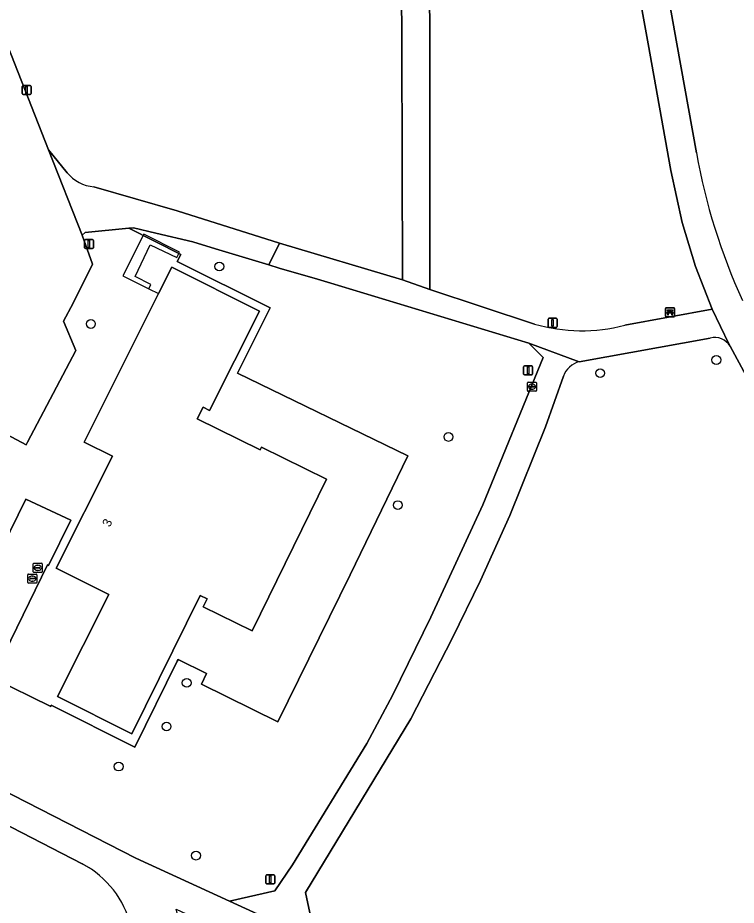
# Model space of a CAD drawing. Extents: x 162417 to 163722, y 384268 to 385417.
# Drawn here: x 162665 to 162744.1, y 384905.1 to 385002.9 of the extents above; entities that cross this region are included whole.
import ezdxf

# ---------------------------------------------------------------- set-up
doc = ezdxf.new("R2010")
doc.units = 0
for name, color, linetype in [('IMGEO_Bank', 7, 'Continuous'), ('IMGEO_Boom', 7, 'Continuous'), ('IMGEO_Erf', 7, 'Continuous'), ('IMGEO_Gemengd_bos', 7, 'Continuous'), ('IMGEO_Groenvoorziening', 7, 'Continuous'), ('IMGEO_Haag', 7, 'Continuous'), ('IMGEO_Hek', 7, 'Continuous'), ('IMGEO_Kolk', 7, 'Continuous'), ('IMGEO_Lichtmast', 7, 'Continuous'), ('IMGEO_Loofbos', 7, 'Continuous'), ('IMGEO_Pand', 7, 'Continuous'), ('IMGEO_Pand_nummerreeks', 7, 'Continuous'), ('IMGEO_Rijbaan_lokaal_gesloten', 7, 'Continuous'), ('IMGEO_Rioolput', 7, 'Continuous'), ('IMGEO_Voetpad_gesloten', 7, 'Continuous'), ('IMGEO_Voetpad_halfverhard', 7, 'Continuous')]:
    doc.layers.add(name, color=color, linetype=linetype)

msp = doc.modelspace()

# ---------------------------------------------------------------- linework, layer by layer
at = {"layer": 'IMGEO_Bank'}
for p, q in [((162736.32, 384969.985), (162736.32, 384970.826)), ((162736.32, 384970.826), (162736.32, 384969.985)), ((162736.395, 384970.91), (162737.236, 384970.91)), ((162737.236, 384970.91), (162736.395, 384970.91)), ((162736.629, 384970.416), (162736.629, 384970.522)), ((162736.673, 384970.522), (162736.673, 384970.416)), ((162736.961, 384970.528), (162736.679, 384970.528)), ((162736.679, 384970.41), (162736.961, 384970.41)), ((162736.967, 384970.416), (162736.967, 384970.522)), ((162737.011, 384970.522), (162737.011, 384970.416)), ((162737.32, 384970.835), (162737.32, 384969.994)), ((162737.32, 384969.994), (162737.32, 384970.835)), ((162737.245, 384969.91), (162736.404, 384969.91)), ((162736.404, 384969.91), (162737.245, 384969.91)), ((162737.017, 384970.308), (162736.624, 384970.308))]:
    msp.add_line(p, q, dxfattribs=at)
for points in [[(162736.567, 384970.308), (162736.425, 384970.308), (162736.537, 384970.41), (162736.623, 384970.41)], [(162736.623, 384970.528), (162736.537, 384970.528), (162736.537, 384970.689), (162737.1, 384970.689), (162737.1, 384970.528), (162737.017, 384970.528)], [(162737.017, 384970.41), (162737.1, 384970.41), (162737.212, 384970.308), (162737.073, 384970.308)], [(162736.617, 384970.301), (162736.617, 384970.094), (162736.574, 384970.094), (162736.574, 384970.301)], [(162737.067, 384970.301), (162737.067, 384970.094), (162737.023, 384970.094), (162737.023, 384970.301)]]:
    msp.add_lwpolyline(points, dxfattribs=at)
for centre, radius, start, end in [((162736.398, 384970.832), 0.0779, 92.4484, 184.28452), ((162736.398, 384970.832), 0.0779, 92.4484, 184.28452), ((162736.622, 384970.521), 0.00671, 2.89567, 87.10433), ((162736.622, 384970.417), 0.00671, 272.89567, 357.10433), ((162736.679, 384970.521), 0.00671, 92.89567, 177.10433), ((162736.679, 384970.417), 0.00671, 182.89567, 267.10433), ((162736.961, 384970.521), 0.00671, 2.89567, 87.10433), ((162736.961, 384970.417), 0.00671, 272.89567, 357.10433), ((162737.018, 384970.521), 0.00671, 92.89567, 177.10433), ((162737.018, 384970.417), 0.00671, 182.89567, 267.10433), ((162737.242, 384970.832), 0.0779, 2.4484, 94.28452), ((162737.242, 384970.832), 0.0779, 2.4484, 94.28452), ((162736.398, 384969.988), 0.0779, 182.4484, 274.28452), ((162736.398, 384969.988), 0.0779, 182.4484, 274.28452), ((162736.567, 384970.301), 0.00671, 2.89567, 87.10433), ((162736.624, 384970.301), 0.00671, 92.89567, 177.10433), ((162737.016, 384970.301), 0.00671, 2.89567, 87.10433), ((162737.073, 384970.301), 0.00671, 92.89567, 177.10433), ((162737.242, 384969.988), 0.0779, 272.4484, 4.28452), ((162737.242, 384969.988), 0.0779, 272.4484, 4.28452)]:
    msp.add_arc(centre, radius, start, end, dxfattribs=at)
at = {"layer": 'IMGEO_Boom'}
for centre in [(162687.199, 384975.461), (162673.043, 384969.131), (162741.935, 384965.159), (162729.134, 384963.709), (162712.429, 384956.683), (162706.852, 384949.167), (162683.603, 384929.586), (162681.378, 384924.773), (162676.1, 384920.36), (162684.623, 384910.552)]:
    msp.add_circle(centre, 0.489, dxfattribs=at)
at = {"layer": 'IMGEO_Erf'}
msp.add_lwpolyline([(162658.984, 384935.79), (162665.87, 384949.817), (162670.825, 384947.525), (162668.388, 384942.524), (162668.279, 384942.581), (162662.168, 384930.151), (162668.625, 384926.977), (162668.685, 384927.112), (162677.9, 384922.487), (162682.565, 384931.955), (162682.641, 384932.158), (162685.793, 384930.619), (162685.237, 384929.448), (162693.634, 384925.29), (162701.607, 384941.49), (162707.971, 384954.6), (162689.204, 384963.718), (162692.784, 384970.914), (162682.547, 384976.006), (162682.943, 384976.767), (162677.219, 384979.675), (162672.421, 384979.213), (162672.076, 384978.896), (162673.226, 384975.731), (162671.101, 384971.409), (162670.042, 384969.431), (162671.375, 384966.217), (162666.08, 384956.114), (162665.925, 384955.818), (162663.79, 384956.941)], dxfattribs=at)
msp.add_lwpolyline([(162675.411, 384954.553), (162672.293, 384956.119), (162680.502, 384972.471), (162681.96, 384975.375), (162691.61, 384970.53), (162686.115, 384959.587), (162685.399, 384959.947), (162684.764, 384958.682), (162691.707, 384955.263), (162691.848, 384955.55), (162698.989, 384952.032), (162690.809, 384935.31), (162685.419, 384937.946), (162685.859, 384938.845), (162685.081, 384939.225), (162677.556, 384923.953), (162669.362, 384928.066), (162675.012, 384939.32), (162669.222, 384942.227)], close=True, dxfattribs=at)
at = {"layer": 'IMGEO_Gemengd_bos'}
msp.add_lwpolyline([(162672.07, 384909.65), (162657.635, 384917.104), (162642.404, 384902.325), (162625.393, 384873.785), (162612.197, 384851.361), (162616.439, 384832.825)], dxfattribs=at)
for centre, radius, start, end in [((162667.115, 384900.122), 10.739, 56.1084, 62.52035), ((162667.261, 384900.356), 10.464, 7.41169, 56.05936)]:
    msp.add_arc(centre, radius, start, end, dxfattribs=at)
at = {"layer": 'IMGEO_Groenvoorziening'}
for points in [[(162649.362, 384924.906), (162677.988, 384910.273), (162688.32, 384905.515), (162693.292, 384906.669), (162695.237, 384909.513), (162703.447, 384922.914), (162706.318, 384928.257), (162710.486, 384936.828), (162716.223, 384949.194), (162722.864, 384965.432), (162721.277, 384966.997), (162699.469, 384973.623), (162698.022, 384974.047), (162693.785, 384975.287), (162692.629, 384975.638), (162686.775, 384977.414), (162684.286, 384978.175), (162680.206, 384979.142), (162677.723, 384979.724), (162677.219, 384979.675), (162682.943, 384976.767), (162682.547, 384976.006), (162692.784, 384970.914), (162689.204, 384963.718), (162707.971, 384954.6), (162701.607, 384941.49), (162693.634, 384925.29), (162685.237, 384929.448), (162685.793, 384930.619), (162682.641, 384932.158), (162682.565, 384931.955), (162677.9, 384922.487), (162668.685, 384927.112), (162668.625, 384926.977), (162662.168, 384930.151), (162668.279, 384942.581), (162668.388, 384942.524), (162670.825, 384947.525), (162665.87, 384949.817), (162658.984, 384935.79)], [(162741.248, 384967.575), (162726.84, 384964.964)], [(162766.925, 384907.1), (162768.008, 384909.584), (162768.293, 384911.192), (162767.743, 384912.987), (162766.989, 384912.798), (162765.701, 384916.53), (162766.445, 384916.8), (162765.082, 384920.804), (162760.396, 384932.895), (162758.923, 384936.287), (162751.438, 384951.872), (162749.254, 384955.923), (162743.449, 384966.69)], [(162725.09, 384963.368), (162723.123, 384957.808), (162719.181, 384948.018), (162715.956, 384940.876), (162712.852, 384934.463), (162708.293, 384925.612), (162696.695, 384906.49), (162697.815, 384901.146)]]:
    msp.add_lwpolyline(points, dxfattribs=at)
for centre, radius, start, end in [((162741.754, 384965.653), 1.987, 31.44635, 104.74452), ((162727.491, 384962.493), 2.556, 104.75993, 159.9697)]:
    msp.add_arc(centre, radius, start, end, dxfattribs=at)
at = {"layer": 'IMGEO_Haag'}
msp.add_lwpolyline([(162679.445, 384973.002), (162679.64, 384973.459), (162677.921, 384974.353), (162679.581, 384977.828), (162682.496, 384976.443), (162682.791, 384977.029), (162678.859, 384979.004), (162676.57, 384974.446)], close=True, dxfattribs=at)
at = {"layer": 'IMGEO_Hek'}
for points in [[(162682.496, 384976.443), (162682.791, 384977.029), (162678.859, 384979.004), (162676.57, 384974.446), (162679.445, 384973.002)], [(162679.445, 384973.002), (162680.502, 384972.471)]]:
    msp.add_lwpolyline(points, dxfattribs=at)
at = {"layer": 'IMGEO_Kolk'}
for p, q in [((162721.122, 384961.79), (162721.122, 384962.642)), ((162721.197, 384962.716), (162722.049, 384962.716)), ((162722.123, 384962.642), (162722.123, 384961.79)), ((162722.049, 384961.716), (162721.197, 384961.716)), ((162721.381, 384962.21), (162721.381, 384962.222)), ((162721.819, 384962.173), (162721.421, 384962.173)), ((162721.424, 384962.259), (162721.822, 384962.259)), ((162721.633, 384961.936), (162721.608, 384961.936)), ((162721.61, 384962.496), (162721.635, 384962.496)), ((162721.865, 384962.222), (162721.865, 384962.21))]:
    msp.add_line(p, q, dxfattribs=at)
for points in [[(162721.122, 384961.79), (162721.122, 384962.642)], [(162721.197, 384962.716), (162722.049, 384962.716)], [(162722.123, 384962.642), (162722.123, 384961.79)], [(162722.049, 384961.716), (162721.197, 384961.716)]]:
    msp.add_lwpolyline(points, dxfattribs=at)
for centre, radius, start, end in [((162721.199, 384962.64), 0.0765, 91.55205, 178.44795), ((162721.199, 384962.64), 0.0765, 91.55205, 178.44795), ((162722.047, 384962.64), 0.0765, 1.55205, 88.44795), ((162722.047, 384962.64), 0.0765, 1.55205, 88.44795), ((162721.199, 384961.792), 0.0765, 181.55205, 268.44795), ((162721.199, 384961.792), 0.0765, 181.55205, 268.44795), ((162721.421, 384962.219), 0.0403, 85.87752, 175.75265), ((162721.418, 384962.209), 0.0366, 178.93798, 274.71019), ((162721.822, 384962.216), 0.043, 264.86636, 352.45326), ((162721.826, 384962.221), 0.0386, 1.73085, 96.63898), ((162722.047, 384961.792), 0.0765, 271.55205, 358.44795), ((162722.047, 384961.792), 0.0765, 271.55205, 358.44795)]:
    msp.add_arc(centre, radius, start, end, dxfattribs=at)
for centre, major_axis, ratio, start_param, end_param in [((162721.609, 384962.216), (-0.387, 0.002), 0.722429, 4.712389, 7.853982), ((162721.634, 384962.216), (-0.39, 0.002), 0.717154, 1.570796, 4.712389)]:
    msp.add_ellipse(centre, major_axis=major_axis, ratio=ratio, start_param=start_param, end_param=end_param, dxfattribs=at)
at = {"layer": 'IMGEO_Lichtmast'}
for p, q in [((162665.471, 384994.503), (162665.471, 384995.303)), ((162665.471, 384995.303), (162665.471, 384994.503)), ((162665.571, 384995.403), (162666.361, 384995.403)), ((162666.361, 384995.403), (162665.571, 384995.403)), ((162666.461, 384995.303), (162666.461, 384994.503)), ((162666.461, 384994.503), (162666.461, 384995.303)), ((162666.361, 384994.403), (162665.571, 384994.403)), ((162665.571, 384994.403), (162666.361, 384994.403)), ((162672.335, 384977.534), (162672.335, 384978.334)), ((162672.335, 384978.334), (162672.335, 384977.534)), ((162672.435, 384978.434), (162673.225, 384978.434)), ((162673.225, 384978.434), (162672.435, 384978.434)), ((162673.325, 384978.334), (162673.325, 384977.534)), ((162673.325, 384977.534), (162673.325, 384978.334)), ((162673.225, 384977.434), (162672.435, 384977.434)), ((162672.435, 384977.434), (162673.225, 384977.434)), ((162723.4, 384968.853), (162723.4, 384969.653)), ((162723.4, 384969.653), (162723.4, 384968.853)), ((162723.5, 384969.753), (162724.29, 384969.753)), ((162724.29, 384969.753), (162723.5, 384969.753)), ((162724.39, 384969.653), (162724.39, 384968.853)), ((162724.39, 384968.853), (162724.39, 384969.653)), ((162724.29, 384968.753), (162723.5, 384968.753)), ((162723.5, 384968.753), (162724.29, 384968.753)), ((162720.708, 384963.614), (162720.708, 384964.414)), ((162720.708, 384964.414), (162720.708, 384963.614)), ((162720.808, 384964.514), (162721.598, 384964.514)), ((162721.598, 384964.514), (162720.808, 384964.514)), ((162721.698, 384964.414), (162721.698, 384963.614)), ((162721.698, 384963.614), (162721.698, 384964.414)), ((162721.598, 384963.514), (162720.808, 384963.514)), ((162720.808, 384963.514), (162721.598, 384963.514)), ((162692.305, 384907.527), (162692.305, 384908.327)), ((162692.305, 384908.327), (162692.305, 384907.527)), ((162692.405, 384908.427), (162693.195, 384908.427)), ((162693.195, 384908.427), (162692.405, 384908.427)), ((162693.295, 384908.327), (162693.295, 384907.527)), ((162693.295, 384907.527), (162693.295, 384908.327)), ((162693.195, 384907.427), (162692.405, 384907.427)), ((162692.405, 384907.427), (162693.195, 384907.427))]:
    msp.add_line(p, q, dxfattribs=at)
for points in [[(162665.891, 384995.278), (162666.041, 384995.278), (162666.041, 384994.528), (162665.891, 384994.528), (162665.891, 384995.278)], [(162672.755, 384978.309), (162672.905, 384978.309), (162672.905, 384977.559), (162672.755, 384977.559), (162672.755, 384978.309)], [(162723.82, 384969.628), (162723.97, 384969.628), (162723.97, 384968.878), (162723.82, 384968.878), (162723.82, 384969.628)], [(162721.128, 384964.389), (162721.278, 384964.389), (162721.278, 384963.639), (162721.128, 384963.639), (162721.128, 384964.389)], [(162692.725, 384908.302), (162692.875, 384908.302), (162692.875, 384907.552), (162692.725, 384907.552), (162692.725, 384908.302)]]:
    msp.add_lwpolyline(points, dxfattribs=at)
for centre, start, end in [((162665.571, 384995.303), 90, 180), ((162665.571, 384995.303), 90, 180), ((162666.361, 384995.303), 0, 90), ((162666.361, 384995.303), 360, 90), ((162665.571, 384994.503), 180, 270), ((162665.571, 384994.503), 180, 270), ((162666.361, 384994.503), 270, 0), ((162666.361, 384994.503), 270, 0), ((162672.435, 384978.334), 90, 180), ((162672.435, 384978.334), 90, 180), ((162673.225, 384978.334), 0, 90), ((162673.225, 384978.334), 360, 90), ((162672.435, 384977.534), 180, 270), ((162672.435, 384977.534), 180, 270), ((162673.225, 384977.534), 270, 0), ((162673.225, 384977.534), 270, 0), ((162723.5, 384969.653), 90, 180), ((162723.5, 384969.653), 90, 180), ((162724.29, 384969.653), 0, 90), ((162724.29, 384969.653), 360, 90), ((162723.5, 384968.853), 180, 270), ((162723.5, 384968.853), 180, 270), ((162724.29, 384968.853), 270, 0), ((162724.29, 384968.853), 270, 0), ((162720.808, 384964.414), 90, 180), ((162720.808, 384964.414), 90, 180), ((162720.808, 384963.614), 180, 270), ((162720.808, 384963.614), 180, 270), ((162721.598, 384964.414), 0, 90), ((162721.598, 384964.414), 360, 90), ((162721.598, 384963.614), 270, 0), ((162721.598, 384963.614), 270, 0), ((162692.405, 384908.327), 90, 180), ((162692.405, 384908.327), 90, 180), ((162693.195, 384908.327), 0, 90), ((162693.195, 384908.327), 360, 90), ((162692.405, 384907.527), 180, 270), ((162692.405, 384907.527), 180, 270), ((162693.195, 384907.527), 270, 0), ((162693.195, 384907.527), 270, 0)]:
    msp.add_arc(centre, 0.1, start, end, dxfattribs=at)
at = {"layer": 'IMGEO_Loofbos'}
for points in [[(162673.382, 384984.237), (162682.546, 384981.593), (162693.813, 384978.04), (162707.352, 384973.986), (162707.274, 385000), (162707.255, 385006.248), (162700.13, 385010.54), (162701.773, 385013.302), (162707.782, 385009.808), (162732.256, 385011.886), (162727.06, 385040.781), (162693.908, 385060.982), (162684.303, 385044.506), (162681.44, 385039.67), (162662.382, 385007.535), (162661.34, 385005.779), (162663.794, 385000), (162663.911, 384999.725), (162668.384, 384988.3), (162670.428, 384985.797)], [(162727.097, 385058.126), (162735.228, 385012.669), (162740.32, 385012.676), (162741.126, 385009.582), (162735.873, 385009.486), (162737.576, 385000), (162739.736, 384987.966)], [(162731.849, 384968.987), (162741.475, 384970.774), (162739.635, 384975.477), (162738.185, 384980.29), (162736.918, 384986.021), (162734.41, 385000), (162732.851, 385008.694), (162710.347, 385006.751), (162710.366, 385000), (162710.38, 384972.938), (162721.916, 384969.121)]]:
    msp.add_lwpolyline(points, dxfattribs=at)
for centre, radius, start, end in [((162807.065, 385000.047), 68.404, 190.17219, 204.45386), ((162673.726, 384988.465), 4.242, 218.97573, 265.34742), ((162727.124, 384986.988), 18.61, 253.74762, 284.70659)]:
    msp.add_arc(centre, radius, start, end, dxfattribs=at)
at = {"layer": 'IMGEO_Pand'}
msp.add_lwpolyline([(162698.989, 384952.032), (162691.848, 384955.55), (162691.707, 384955.263), (162684.764, 384958.682), (162685.399, 384959.947), (162686.115, 384959.587), (162691.61, 384970.53), (162681.96, 384975.375), (162680.502, 384972.471), (162672.293, 384956.119), (162675.411, 384954.553), (162669.222, 384942.227), (162675.012, 384939.32), (162669.362, 384928.066), (162677.556, 384923.953), (162685.081, 384939.225), (162685.859, 384938.845), (162685.419, 384937.946), (162690.809, 384935.31)], close=True, dxfattribs=at)
at = {"layer": 'IMGEO_Rijbaan_lokaal_gesloten'}
msp.add_lwpolyline([(162710.366, 385000), (162710.347, 385006.751), (162732.851, 385008.694), (162732.256, 385011.886), (162707.782, 385009.808), (162701.773, 385013.302), (162700.13, 385010.54), (162707.255, 385006.248), (162707.274, 385000), (162707.352, 384973.986), (162710.38, 384972.938)], close=True, dxfattribs=at)
for points in [[(162662.457, 384957.642), (162663.79, 384956.941), (162665.925, 384955.818), (162666.08, 384956.114), (162671.375, 384966.217), (162670.042, 384969.431), (162671.101, 384971.409), (162673.226, 384975.731), (162672.076, 384978.896), (162668.384, 384988.3), (162663.911, 384999.725), (162663.794, 385000), (162661.34, 385005.779)], [(162670.428, 384985.797), (162668.384, 384988.3), (162672.076, 384978.896), (162672.421, 384979.213), (162677.219, 384979.675), (162677.723, 384979.724), (162680.206, 384979.142), (162684.286, 384978.175), (162686.775, 384977.414), (162692.629, 384975.638), (162693.813, 384978.04), (162682.546, 384981.593)], [(162682.546, 384981.593), (162673.382, 384984.237)], [(162721.916, 384969.121), (162710.38, 384972.938), (162707.352, 384973.986), (162693.813, 384978.04), (162692.629, 384975.638), (162693.785, 384975.287), (162698.022, 384974.047), (162699.469, 384973.623), (162721.277, 384966.997), (162726.84, 384964.964), (162741.248, 384967.575)], [(162741.475, 384970.774), (162731.849, 384968.987)], [(162743.449, 384966.69), (162743.321, 384966.952), (162741.475, 384970.774)]]:
    msp.add_lwpolyline(points, dxfattribs=at)
for centre, radius, start, end in [((162673.726, 384988.465), 4.242, 218.97573, 265.34742), ((162727.124, 384986.988), 18.61, 253.74762, 284.70659), ((162741.754, 384965.653), 1.987, 31.44635, 104.74452)]:
    msp.add_arc(centre, radius, start, end, dxfattribs=at)
at = {"layer": 'IMGEO_Rioolput'}
for p, q in [((162666.693, 384941.828), (162666.693, 384942.68)), ((162666.768, 384942.754), (162667.62, 384942.754)), ((162666.952, 384942.248), (162666.952, 384942.26)), ((162667.39, 384942.211), (162666.992, 384942.211)), ((162666.995, 384942.297), (162667.393, 384942.297)), ((162667.181, 384942.534), (162667.206, 384942.534)), ((162667.436, 384942.26), (162667.436, 384942.248)), ((162667.694, 384942.68), (162667.694, 384941.828)), ((162666.088, 384940.649), (162666.088, 384941.501)), ((162666.163, 384941.575), (162667.015, 384941.575)), ((162666.347, 384941.069), (162666.347, 384941.081)), ((162666.39, 384941.118), (162666.788, 384941.118)), ((162666.576, 384941.355), (162666.601, 384941.355)), ((162667.62, 384941.754), (162666.768, 384941.754)), ((162666.831, 384941.081), (162666.831, 384941.069)), ((162667.089, 384941.501), (162667.089, 384940.649)), ((162667.204, 384941.974), (162667.179, 384941.974)), ((162667.015, 384940.575), (162666.163, 384940.575)), ((162666.785, 384941.032), (162666.387, 384941.032)), ((162666.599, 384940.795), (162666.574, 384940.795))]:
    msp.add_line(p, q, dxfattribs=at)
for points in [[(162666.693, 384941.828), (162666.693, 384942.68)], [(162666.768, 384942.754), (162667.62, 384942.754)], [(162667.694, 384942.68), (162667.694, 384941.828)], [(162666.088, 384940.649), (162666.088, 384941.501)], [(162666.163, 384941.575), (162667.015, 384941.575)], [(162667.62, 384941.754), (162666.768, 384941.754)], [(162667.089, 384941.501), (162667.089, 384940.649)], [(162667.015, 384940.575), (162666.163, 384940.575)]]:
    msp.add_lwpolyline(points, dxfattribs=at)
for centre, radius, start, end in [((162666.77, 384942.678), 0.0765, 91.55205, 178.44795), ((162666.77, 384942.678), 0.0765, 91.55205, 178.44795), ((162666.992, 384942.257), 0.0403, 85.87752, 175.75265), ((162666.989, 384942.247), 0.0366, 178.93798, 274.71019), ((162667.393, 384942.254), 0.043, 264.86636, 352.45326), ((162667.397, 384942.259), 0.0386, 1.73085, 96.63898), ((162667.618, 384942.678), 0.0765, 1.55205, 88.44795), ((162667.618, 384942.678), 0.0765, 1.55205, 88.44795), ((162666.165, 384941.499), 0.0765, 91.55205, 178.44795), ((162666.165, 384941.499), 0.0765, 91.55205, 178.44795), ((162666.387, 384941.078), 0.0403, 85.87752, 175.75265), ((162666.384, 384941.068), 0.0366, 178.93798, 274.71019), ((162666.77, 384941.83), 0.0765, 181.55205, 268.44795), ((162666.77, 384941.83), 0.0765, 181.55205, 268.44795), ((162666.788, 384941.075), 0.043, 264.86636, 352.45326), ((162666.792, 384941.08), 0.0386, 1.73085, 96.63898), ((162667.013, 384941.499), 0.0765, 1.55205, 88.44795), ((162667.013, 384941.499), 0.0765, 1.55205, 88.44795), ((162667.618, 384941.83), 0.0765, 271.55205, 358.44795), ((162667.618, 384941.83), 0.0765, 271.55205, 358.44795), ((162666.165, 384940.651), 0.0765, 181.55205, 268.44795), ((162666.165, 384940.651), 0.0765, 181.55205, 268.44795), ((162667.013, 384940.651), 0.0765, 271.55205, 358.44795), ((162667.013, 384940.651), 0.0765, 271.55205, 358.44795)]:
    msp.add_arc(centre, radius, start, end, dxfattribs=at)
for centre, major_axis, ratio, start_param, end_param in [((162667.18, 384942.254), (-0.387, 0.002), 0.722429, 4.712389, 7.853982), ((162667.205, 384942.254), (-0.39, 0.002), 0.717154, 1.570796, 4.712389), ((162666.575, 384941.075), (-0.387, 0.002), 0.722429, 4.712389, 7.853982), ((162666.6, 384941.075), (-0.39, 0.002), 0.717154, 1.570796, 4.712389)]:
    msp.add_ellipse(centre, major_axis=major_axis, ratio=ratio, start_param=start_param, end_param=end_param, dxfattribs=at)
at = {"layer": 'IMGEO_Voetpad_gesloten'}
for points in [[(162688.32, 384905.515), (162677.988, 384910.273), (162649.362, 384924.906), (162648.251, 384926.739), (162647.595, 384925.546), (162647.419, 384925.216)], [(162647.063, 384922.563), (162657.635, 384917.104), (162672.07, 384909.65)], [(162677.637, 384901.706), (162680.405, 384890.897), (162680.91, 384889.336), (162684.9, 384894.85), (162682.431, 384904.641), (162689.669, 384901.253), (162694.073, 384902.867), (162688.32, 384905.515)]]:
    msp.add_lwpolyline(points, dxfattribs=at)
for centre, radius, start, end in [((162667.115, 384900.122), 10.739, 56.1084, 62.52035), ((162667.261, 384900.356), 10.464, 7.41169, 56.05936)]:
    msp.add_arc(centre, radius, start, end, dxfattribs=at)
at = {"layer": 'IMGEO_Voetpad_halfverhard'}
for points in [[(162739.736, 384987.966), (162737.576, 385000), (162735.873, 385009.486), (162741.126, 385009.582), (162740.32, 385012.676), (162735.228, 385012.669), (162727.097, 385058.126)], [(162724.077, 385056.903), (162726.127, 385045.155), (162727.06, 385040.781), (162732.256, 385011.886), (162732.851, 385008.694), (162734.41, 385000), (162736.918, 384986.021), (162738.185, 384980.29), (162739.635, 384975.477), (162741.475, 384970.774), (162743.321, 384966.952), (162743.449, 384966.69), (162749.254, 384955.923), (162751.438, 384951.872), (162758.923, 384936.287), (162760.396, 384932.895), (162765.082, 384920.804), (162766.445, 384916.8), (162767.743, 384912.987), (162768.293, 384911.192), (162768.008, 384909.584), (162766.925, 384907.1)], [(162726.84, 384964.964), (162721.277, 384966.997), (162722.864, 384965.432), (162716.223, 384949.194), (162710.486, 384936.828), (162706.318, 384928.257), (162703.447, 384922.914), (162695.237, 384909.513), (162693.292, 384906.669), (162688.32, 384905.515), (162694.073, 384902.867), (162696.347, 384901.82), (162697.815, 384901.146), (162696.695, 384906.49), (162708.293, 384925.612)], [(162708.293, 384925.612), (162712.852, 384934.463), (162715.956, 384940.876), (162719.181, 384948.018), (162723.123, 384957.808), (162725.09, 384963.368)]]:
    msp.add_lwpolyline(points, dxfattribs=at)
for centre, radius, start, end in [((162807.065, 385000.047), 68.404, 190.17219, 204.45386), ((162727.491, 384962.493), 2.556, 104.75993, 159.9697)]:
    msp.add_arc(centre, radius, start, end, dxfattribs=at)

# ---------------------------------------------------------------- texts
at = {"layer": 'IMGEO_Pand_nummerreeks'}
msp.add_text('3', height=1, rotation=63.34048, dxfattribs=at).set_placement((162675.124, 384946.673))

doc.saveas('drawing.dxf')
